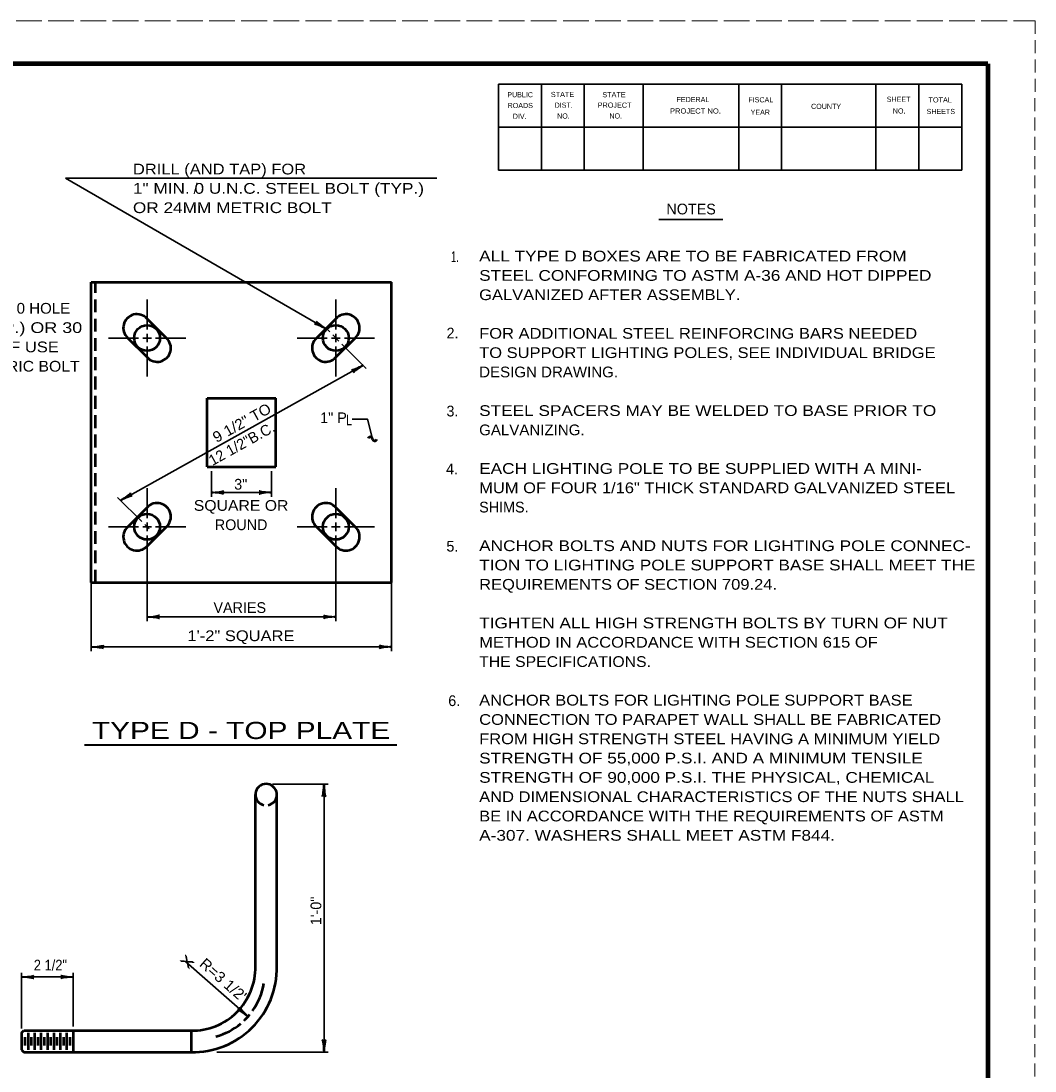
# Model space of a CAD drawing. Extents: x -1 to 679, y 0 to 440.
# Drawn here: x 442.6 to 679, y 195.1 to 439.8 of the extents above; entities that cross this region are included whole.
import ezdxf
from ezdxf.enums import TextEntityAlignment as Align

# ---------------------------------------------------------------- set-up
doc = ezdxf.new("R2010")
doc.units = 0
doc.linetypes.add('LONG_DASHED', pattern=[7.5, 6, -1.5])
doc.linetypes.add('MEDIUM_DASHED', pattern=[4.5, 3, -1.5])
doc.layers.add('1', color=7, linetype='Continuous', lineweight=35)
doc.layers.add('61', color=7, linetype='Continuous', lineweight=35)

msp = doc.modelspace()

# ---------------------------------------------------------------- linework, layer by layer
at = {"layer": '1', "linetype": 'MEDIUM_DASHED', "lineweight": 13}
msp.add_line((679.025, 439.78), (679.005, -0.24), dxfattribs=at)
at = {"layer": '1'}
for p, q in [((452.986, 403.113), (539.624, 403.113)), ((452.986, 403.113), (513.771, 368.023)), ((591.352, 393.532), (606.239, 393.532)), ((472.04, 367.894), (472.04, 374.894)), ((516.04, 367.894), (516.04, 374.894)), ((513.848, 368.086), (514.626, 367.308)), ((470.04, 365.894), (463.04, 365.894)), ((474.04, 365.894), (481.04, 365.894)), ((514.04, 365.894), (507.04, 365.894)), ((515.333, 366.601), (516.747, 365.187)), ((518.04, 365.894), (525.04, 365.894)), ((472.04, 363.894), (472.04, 356.894)), ((516.04, 363.894), (516.04, 356.894)), ((517.455, 364.48), (523.112, 358.823)), ((465.884, 328.051), (522.404, 359.53)), ((487.04, 334.894), (487.04, 328.894)), ((501.04, 334.894), (501.04, 328.894)), ((472.04, 323.894), (472.04, 330.894)), ((516.04, 323.894), (516.04, 330.894)), ((465.177, 328.758), (470.833, 323.101)), ((487.04, 329.894), (501.04, 329.894)), ((470.04, 321.894), (463.04, 321.894)), ((471.54, 322.394), (472.54, 321.394)), ((474.04, 321.894), (481.04, 321.894)), ((514.04, 321.894), (507.04, 321.894)), ((518.04, 321.894), (525.04, 321.894)), ((472.04, 319.894), (472.04, 299.894)), ((516.04, 319.894), (516.04, 299.894)), ((459.04, 308.894), (459.04, 292.894)), ((529.04, 308.894), (529.04, 292.894)), ((472.04, 300.894), (516.04, 300.894)), ((459.04, 293.894), (529.04, 293.894)), ((501.291, 261.913), (514.291, 261.913)), ((513.291, 261.913), (513.291, 199.463)), ((495.574, 207.743), (481.047, 220.525)), ((442.791, 204.963), (442.791, 217.963)), ((454.791, 205.463), (454.791, 217.963)), ((442.791, 216.963), (454.791, 216.963)), ((488.291, 199.463), (514.291, 199.463))]:
    msp.add_line(p, q, dxfattribs=at)
at = {"layer": '1', "lineweight": 53}
for p, q in [((459.04, 308.894), (459.04, 378.894)), ((459.04, 378.894), (529.04, 378.894)), ((529.04, 308.894), (529.04, 378.894)), ((472.04, 370.394), (476.54, 365.894)), ((516.04, 370.394), (511.54, 365.894)), ((472.04, 361.394), (467.54, 365.894)), ((516.04, 361.394), (520.54, 365.894)), ((486.04, 335.894), (486.04, 351.894)), ((486.04, 351.894), (502.04, 351.894)), ((502.04, 335.894), (502.04, 351.894)), ((486.04, 335.894), (502.04, 335.894)), ((472.04, 326.394), (467.54, 321.894)), ((516.04, 326.394), (520.54, 321.894)), ((472.04, 317.394), (476.54, 321.894)), ((516.04, 317.394), (511.54, 321.894)), ((459.04, 308.894), (529.04, 308.894)), ((497.291, 219.463), (497.291, 259.463)), ((502.291, 219.463), (502.291, 259.463)), ((442.791, 203.963), (443.291, 204.463)), ((442.791, 203.963), (442.791, 199.963)), ((443.291, 204.463), (482.291, 204.463)), ((444.291, 203.963), (444.291, 199.963)), ((445.791, 203.963), (445.791, 199.963)), ((447.291, 203.963), (447.291, 199.963)), ((448.791, 203.963), (448.791, 199.963)), ((450.291, 203.963), (450.291, 199.963)), ((451.791, 203.963), (451.791, 199.963)), ((453.291, 203.963), (453.291, 199.963)), ((454.791, 204.463), (454.791, 199.463)), ((482.291, 204.463), (482.291, 199.463)), ((443.541, 202.963), (443.541, 200.963)), ((445.041, 202.963), (445.041, 200.963)), ((446.541, 202.963), (446.541, 200.963)), ((448.041, 202.963), (448.041, 200.963)), ((449.541, 202.963), (449.541, 200.963)), ((451.041, 202.963), (451.041, 200.963)), ((452.541, 202.963), (452.541, 200.963)), ((454.041, 202.963), (454.041, 200.963)), ((442.791, 199.963), (443.291, 199.463)), ((443.291, 199.463), (482.291, 199.463))]:
    msp.add_line(p, q, dxfattribs=at)
at = {"layer": '1', "linetype": 'MEDIUM_DASHED', "lineweight": 53}
msp.add_line((460.04, 308.894), (460.04, 378.894), dxfattribs=at)
at = {"layer": '1', "lineweight": 40}
msp.add_line((457.441, 271.091), (530.279, 271.091), dxfattribs=at)
at = {"layer": '1'}
for points in [[(471.04, 365.894), (472.04, 365.894), (473.04, 365.894)], [(472.04, 364.894), (472.04, 365.894), (472.04, 366.894)], [(517.04, 365.894), (516.04, 365.894), (515.04, 365.894)], [(516.04, 364.894), (516.04, 365.894), (516.04, 366.894)], [(524.572, 342.387), (523.42, 347.015), (519.866, 347.015)], [(471.04, 321.894), (472.04, 321.894), (473.04, 321.894)], [(472.04, 322.894), (472.04, 321.894), (472.04, 320.894)], [(517.04, 321.894), (516.04, 321.894), (515.04, 321.894)], [(516.04, 322.894), (516.04, 321.894), (516.04, 320.894)]]:
    msp.add_lwpolyline(points, dxfattribs=at)
at = {"layer": '1', "lineweight": 53}
for centre in [(472.04, 365.894), (516.04, 365.894), (472.04, 321.894), (516.04, 321.894)]:
    msp.add_circle(centre, 3, dxfattribs=at)
for centre, radius, start, end in [((469.684, 368.25), 3.186, 42.29136, 227.70864), ((518.397, 368.25), 3.186, 312.29136, 137.70864), ((474.397, 363.538), 3.186, 222.29136, 47.70864), ((513.684, 363.538), 3.186, 132.29136, 317.70864), ((524.064, 342.318), 0.513, 7.71531, 162.28469), ((525.08, 342.455), 0.513, 187.71531, 342.28469), ((474.397, 324.25), 3.186, 312.29136, 137.70864), ((513.684, 324.25), 3.186, 42.29136, 227.70864), ((469.684, 319.538), 3.186, 132.29136, 317.70864), ((518.397, 319.538), 3.186, 222.29136, 47.70864), ((499.791, 259.463), 2.5, 281.53696, 258.46304), ((482.567, 219.188), 14.727, 268.92697, 1.07303), ((482.708, 219.047), 19.588, 268.78134, 1.21866), ((483.972, 218.057), 15.524, 324.48804, 350.40705), ((483.972, 218.057), 15.524, 313.39217, 320.77939), ((483.972, 218.057), 15.524, 285.43733, 309.6831)]:
    msp.add_arc(centre, radius, start, end, dxfattribs=at)
at = {"layer": '1', "lineweight": 40}
for centre, major_axis, ratio, start_param, end_param in [((512.906, 368.766), (-1.433, 1.03), 0.07063, 6.2823074, 8.5597026), ((512.687, 368.329), (1.625, -0.758), 0.122415, 0.8963533, 3.1415927), ((521.323, 359.17), (-1.62, -0.701), 0.07063, 6.2823074, 8.5597026), ((521.586, 358.758), (1.484, 1.005), 0.122415, 0.8963533, 3.1415927), ((466.703, 328.824), (-1.484, -1.005), 0.122415, 0.8963533, 3.1415927), ((466.703, 328.824), (-1.484, -1.005), 0.122415, 0.8963533, 3.1415927), ((466.966, 328.412), (1.62, 0.701), 0.07063, 6.2823074, 8.5597026), ((466.966, 328.412), (1.62, 0.701), 0.07063, 6.2823074, 8.5597026), ((488.161, 329.682), (-1.756, 0.176), 0.07063, 3.1407148, 5.41811), ((488.161, 329.682), (-1.756, 0.176), 0.07063, 3.1407148, 5.41811), ((488.132, 330.17), (-1.786, -0.156), 0.122415, 0.8963533, 3.1415927), ((488.132, 330.17), (-1.786, -0.156), 0.122415, 0.8963533, 3.1415927), ((499.949, 329.618), (1.786, 0.156), 0.122415, 0.8963533, 3.1415927), ((499.92, 330.106), (1.756, -0.176), 0.07063, 3.1407148, 5.41811), ((473.132, 301.17), (-1.786, -0.156), 0.122415, 0.8963533, 3.1415927), ((473.132, 301.17), (-1.786, -0.156), 0.122415, 0.8963533, 3.1415927), ((514.92, 301.106), (1.756, -0.176), 0.07063, 3.1407148, 5.41811), ((473.161, 300.682), (-1.756, 0.176), 0.07063, 3.1407148, 5.41811), ((473.161, 300.682), (-1.756, 0.176), 0.07063, 3.1407148, 5.41811), ((514.949, 300.618), (1.786, 0.156), 0.122415, 0.8963533, 3.1415927), ((460.161, 293.682), (-1.756, 0.176), 0.07063, 3.1407148, 5.41811), ((460.132, 294.17), (-1.786, -0.156), 0.122415, 0.8963533, 3.1415927), ((527.949, 293.618), (1.786, 0.156), 0.122415, 0.8963533, 3.1415927), ((527.92, 294.106), (1.756, -0.176), 0.07063, 3.1407148, 5.41811), ((513.079, 260.792), (0.176, 1.756), 0.07063, 3.1407148, 5.41811), ((513.079, 260.792), (0.176, 1.756), 0.07063, 3.1407148, 5.41811), ((513.567, 260.822), (-0.156, 1.786), 0.122415, 0.8963533, 3.1415927), ((513.567, 260.822), (-0.156, 1.786), 0.122415, 0.8963533, 3.1415927), ((443.882, 217.24), (-1.786, -0.156), 0.122415, 0.8963533, 3.1415927), ((443.882, 217.24), (-1.786, -0.156), 0.122415, 0.8963533, 3.1415927), ((443.912, 216.752), (-1.756, 0.176), 0.07063, 3.1407148, 5.41811), ((443.912, 216.752), (-1.756, 0.176), 0.07063, 3.1407148, 5.41811), ((453.7, 216.687), (1.786, 0.156), 0.122415, 0.8963533, 3.1415927), ((453.67, 217.175), (1.756, -0.176), 0.07063, 3.1407148, 5.41811), ((494.572, 208.256), (1.444, -1.062), 0.122415, 0.8963533, 3.1415927), ((494.872, 208.642), (-1.203, 1.292), 0.07063, 6.2823074, 8.5597026), ((513.015, 200.555), (0.156, -1.786), 0.122415, 0.8963533, 3.1415927), ((513.503, 200.584), (-0.176, -1.756), 0.07063, 3.1407148, 5.41811)]:
    msp.add_ellipse(centre, major_axis=major_axis, ratio=ratio, start_param=start_param, end_param=end_param, dxfattribs=at)
at = {"layer": '61', "linetype": 'LONG_DASHED', "lineweight": 13}
msp.add_line((-0.995, 439.78), (679.025, 439.78), dxfattribs=at)
at = {"layer": '61', "lineweight": 158}
msp.add_line((668.045, 429.78), (668.065, 9.74), dxfattribs=at)
at = {"layer": '61'}
for p, q in [((563.965, 425.02), (563.965, 405.02)), ((573.965, 425.02), (573.965, 405.02)), ((587.645, 425.02), (587.645, 405.02)), ((609.965, 425.02), (609.965, 405.02)), ((619.965, 425.02), (619.965, 405.02)), ((641.945, 425.04), (641.945, 405.04)), ((651.945, 425.04), (651.945, 405.04)), ((661.965, 415), (553.945, 415.02))]:
    msp.add_line(p, q, dxfattribs=at)
at = {"layer": '61', "lineweight": 158}
msp.add_lwpolyline([(668.045, 429.78), (29.005, 429.78), (29.005, 9.76)], dxfattribs=at)
at = {"layer": '61'}
for points in [[(661.945, 425.04), (553.965, 425.02), (553.965, 405.02)], [(661.945, 425.04), (661.945, 405.04), (553.965, 405.02)]]:
    msp.add_lwpolyline(points, dxfattribs=at)

# ---------------------------------------------------------------- texts
at = {"layer": '1'}
for s, height, width, p in [('DRILL (AND TAP) FOR', 2.5, 1.15, (468.742, 404.016)), ('1" MIN. 0 U.N.C. STEEL BOLT (TYP.)', 2.5, 1.2, (468.742, 399.516)), ('OR 24MM METRIC BOLT', 2.5, 1.2, (468.742, 395.016)), ('1.', 2.5, 0.65, (542.9, 383.59)), ('ALL TYPE D BOXES ARE TO BE FABRICATED FROM', 2.5, 1.2, (549.453, 383.728)), ('STEEL CONFORMING TO ASTM A-36 AND HOT DIPPED', 2.5, 1.2, (549.453, 379.228)), ('GALVANIZED AFTER ASSEMBLY.', 2.5, 1.15, (549.453, 374.728)), ('1 1/4" 0 HOLE', 2.5, 1.05, (431.606, 371.566)), ('(TYP.) OR 30', 2.5, 1.25, (431.606, 367.066)), ('FOR ADDITIONAL STEEL REINFORCING BARS NEEDED', 2.5, 1.15, (549.453, 365.728)), ('MM IF USE', 2.5, 1.15, (431.606, 362.566)), ('TO SUPPORT LIGHTING POLES, SEE INDIVIDUAL BRIDGE', 2.5, 1.15, (549.453, 361.228)), ('METRIC BOLT', 2.5, 1.1, (431.606, 358.066)), ('DESIGN DRAWING.', 2.5, 1.05, (549.453, 356.728)), ('STEEL SPACERS MAY BE WELDED TO BASE PRIOR TO', 2.5, 1.2, (549.453, 347.728)), ('L', 2.5, 0.75, (518.425, 345.554)), ('GALVANIZING.', 2.5, 1.05, (549.453, 343.228)), ('EACH LIGHTING POLE TO BE SUPPLIED WITH A MINI-', 2.5, 1.2, (549.453, 334.228)), ('MUM OF FOUR 1/16" THICK STANDARD GALVANIZED STEEL', 2.5, 1.15, (549.453, 329.728)), ('ANCHOR BOLTS AND NUTS FOR LIGHTING POLE CONNEC-', 2.5, 1.2, (549.453, 316.228)), ('TION TO LIGHTING POLE SUPPORT BASE SHALL MEET THE', 2.5, 1.2, (549.453, 311.728)), ('REQUIREMENTS OF SECTION 709.24.', 2.5, 1.15, (549.453, 307.228)), ('TIGHTEN ALL HIGH STRENGTH BOLTS BY TURN OF NUT', 2.5, 1.2, (549.453, 298.228)), ('1\'-2" SQUARE', 2.5, 1.15, (481.447, 295.246)), ('METHOD IN ACCORDANCE WITH SECTION 615 OF', 2.5, 1.15, (549.453, 293.728)), ('THE SPECIFICATIONS.', 2.5, 1.1, (549.453, 289.228)), ('ANCHOR BOLTS FOR LIGHTING POLE SUPPORT BASE', 2.5, 1.15, (549.453, 280.228)), ('CONNECTION TO PARAPET WALL SHALL BE FABRICATED', 2.5, 1.15, (549.453, 275.728)), ('TYPE D - TOP PLATE', 4, 1.3, (459.175, 272.431)), ('FROM HIGH STRENGTH STEEL HAVING A MINIMUM YIELD', 2.5, 1.15, (549.453, 271.228)), ('STRENGTH OF 55,000 P.S.I. AND A MINIMUM TENSILE', 2.5, 1.2, (549.453, 266.728)), ('STRENGTH OF 90,000 P.S.I. THE PHYSICAL, CHEMICAL', 2.5, 1.2, (549.453, 262.228)), ('AND DIMENSIONAL CHARACTERISTICS OF THE NUTS SHALL', 2.5, 1.15, (549.453, 257.728)), ('BE IN ACCORDANCE WITH THE REQUIREMENTS OF ASTM', 2.5, 1.15, (549.453, 253.228)), ('A-307. WASHERS SHALL MEET ASTM F844.', 2.5, 1.2, (549.453, 248.728)), ('2 1/2"', 2.5, 0.9, (445.627, 218.481))]:
    msp.add_text(s, height=height, dxfattribs=dict(at, width=width)).set_placement(p)
for s, p in [('/', (482.878, 399.49)), ('NOTES', (593.104, 394.706)), ('2.', (541.848, 365.791)), ('3.', (541.834, 347.61)), ('1" P', (512.396, 346.05)), ('4.', (541.732, 334.13)), ('3"', (492.349, 330.564)), ('SHIMS.', (549.453, 325.228)), ('5.', (541.815, 316.115)), ('VARIES', (487.517, 301.814)), ('6.', (542.252, 280.112))]:
    msp.add_text(s, height=2.5, dxfattribs=at).set_placement(p)
for s, rotation, width, p in [('9 1/2" TO', 29.116, 1.05, (488.224, 341.416)), ('x', 318.655, 2.05, (479.463, 220.94)), ('R=3 1/2"', 318.655, 1.05, (484.051, 219.714))]:
    msp.add_text(s, height=2.5, rotation=rotation, dxfattribs=dict(at, width=width)).set_placement(p)
for s, rotation, p in [('12 1/2"B.C.', 29.116, (487.279, 336.036)), ('1\'-0"', 90, (512.651, 229.039))]:
    msp.add_text(s, height=2.5, rotation=rotation, dxfattribs=at).set_placement(p)
at = {"layer": '1', "width": 1.1}
msp.add_text('SQUARE OR', height=2.5, dxfattribs=at).set_placement((493.959, 325.616), align=Align.CENTER)
at = {"layer": '1'}
msp.add_text('ROUND', height=2.5, dxfattribs=at).set_placement((493.959, 321.116), align=Align.CENTER)
at = {"layer": '61'}
for s, rotation, p in [('PUBLIC', 0.033, (556.005, 422)), ('FEDERAL', 0.007, (595.465, 420.88)), ('FISCAL', 359.942, (612.205, 420.82)), ('SHEET', 0.059, (644.465, 420.94)), ('ROADS', 0.124, (556.085, 419.48)), ('DIST.', 0.056, (567.045, 419.56)), ('YEAR', 0.105, (612.725, 417.92)), ('COUNTY', 0.069, (626.825, 419.28)), ('SHEETS', 359.959, (653.745, 418.1)), ('DIV.', 359.932, (557.285, 416.98))]:
    msp.add_text(s, height=1.201, rotation=rotation, dxfattribs=at).set_placement(p)
for s, rotation, width, p in [('STATE', 0.059, 1.05, (566.165, 422.06)), ('STATE', 0.059, 1.05, (578.165, 422)), ('TOTAL', 359.926, 1.05, (654.205, 420.8)), ('PROJECT', 359.908, 1.05, (577.085, 419.58)), ('PROJECT NO.', 359.922, 1.1, (593.925, 418.22)), ('NO.', 359.852, 0.95, (645.885, 418.22)), ('NO.', 359.852, 0.95, (567.625, 417.04)), ('NO.', 0.225, 0.95, (579.825, 417.04))]:
    msp.add_text(s, height=1.201, rotation=rotation, dxfattribs=dict(at, width=width)).set_placement(p)

doc.saveas('drawing.dxf')
